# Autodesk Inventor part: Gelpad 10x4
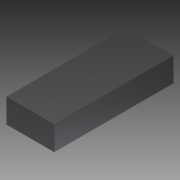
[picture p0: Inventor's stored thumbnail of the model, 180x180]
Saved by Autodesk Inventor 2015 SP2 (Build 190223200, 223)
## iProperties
Created: 2015-08
Part Number: Gelpad 10x4
Material: Gummi, Silikon
Document SubType Name: Modeling
Designer: ryll
Mass: 0.125 g
Surface Area: 1.6 cm^2
Volume: 0.1 cm^3
Density: 1.25 g/cm^3
Appearance: Gummi - schwarz - Version 1.1
Author: ryll
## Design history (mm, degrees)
sketch "Skizze1"
  geometry: L1 (-2, 5)-(2, 5); L2 (2, 5)-(2, -5); L3 (2, -5)-(-2, -5); L4 (-2, -5)-(-2, 5); L5 (-2.8, 0)-(2.8, 0) reference; L6 (0, 7)-(0, -7) reference; 1 further point
  constraints: 8 end point, 2 parallel, 1 horizontal, 1 perpendicular, 2 other
  dimensions: "d0" = 4 distance of L1.start L1.end; "d1" = 10 distance of L1.end L2.end
extrude "Extrusion1" new body sketch "Skizze1" distance "d2" = 2; taper "d3" = 0 deg
node "Volumenkörper1"
